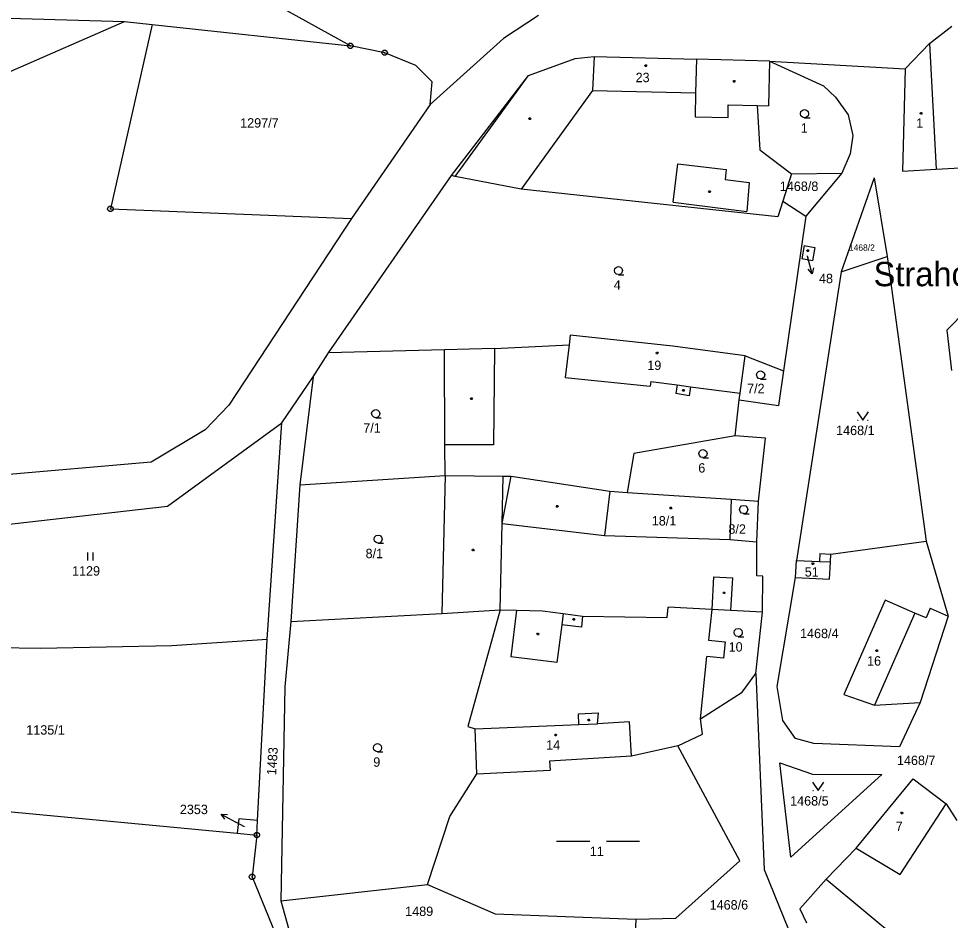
# Model space of a CAD drawing. Extents: x -852001 to -848657, y -1054973 to -1052182.
# Drawn here: x -850781 to -850612.8, y -1053593.3 to -1053430.4 of the extents above; entities that cross this region are included whole.
import ezdxf

# ---------------------------------------------------------------- set-up
doc = ezdxf.new("R2010")
doc.units = 0
for name, color, linetype in [('KN_HRANICE', 7, 'Continuous'), ('KN_KULTURY', 7, 'Continuous'), ('KN_MEZNIKY', 7, 'Continuous'), ('KN_PARCELY', 7, 'Continuous'), ('KN_SLUCKY', 7, 'Continuous'), ('KN_STAVEBNI', 7, 'Continuous')]:
    doc.layers.add(name, color=color, linetype=linetype)

# ---------------------------------------------------------------- blocks, each defined once
blk = doc.blocks.new('304')
blk.add_lwpolyline([(0, 0), (-0.38, 0.1), (-0.65, 0.37), (-0.75, 0.74), (-0.65, 1.11), (-0.38, 1.38), (-0.01, 1.48), (0.36, 1.38), (0.63, 1.11), (0.73, 0.73), (0.63, 0.35), (0.36, 0.08), (-0.02, -0.02), (0.98, -0.02)])
blk = doc.blocks.new('306')
for p, q in [((-0.5, 1.5), (-0.5, 0)), ((0.5, 0), (0.5, 1.5))]:
    blk.add_line(p, q)
blk = doc.blocks.new('314')
for p, q in [((-0.95, 0), (-0.85, 0)), ((0.85, 0), (0.95, 0))]:
    blk.add_line(p, q)
blk.add_lwpolyline([(-1, 1.5), (0, 0), (1, 1.5)])
blk = doc.blocks.new('803')
for p, q in [((-7.5, 0), (-1.5, 0)), ((1.5, 0), (7.5, 0))]:
    blk.add_line(p, q)
blk = doc.blocks.new('10292')
blk.add_line((0, 3), (0, 0))
blk.add_lwpolyline([(-0.5, 2), (0, 3), (0.5, 2)])
blk = doc.blocks.new('402')
blk.add_lwpolyline([(0.09, 0.15), (0.18, 0), (0.09, -0.15), (-0.09, -0.15), (-0.18, 0), (-0.09, 0.15), (0.09, 0.15)])
blk = doc.blocks.new('105')
blk.add_line((-0.12, 0), (0.12, 0))
blk.add_lwpolyline([(0.15, 0.48), (0.4, 0.3), (0.5, 0.01), (0.4, -0.28), (0.15, -0.46), (-0.16, -0.46), (-0.41, -0.28), (-0.51, 0.01), (-0.41, 0.3), (-0.16, 0.48), (0.15, 0.48)])

msp = doc.modelspace()

# ---------------------------------------------------------------- linework, layer by layer
at = {"layer": 'KN_HRANICE'}
for p, q in [((-850800.29, -1053429.81), (-850761.82, -1053430.94)), ((-850721.08, -1053435.35), (-850732.58, -1053428.94)), ((-850687.09, -1053429.83), (-850693.44, -1053434)), ((-850782.51, -1053439.96), (-850761.82, -1053430.94)), ((-850756.84, -1053431.48), (-850764.38, -1053464.76)), ((-850761.82, -1053430.94), (-850756.84, -1053431.48)), ((-850756.84, -1053431.48), (-850721.08, -1053435.35)), ((-850616.53, -1053434.88), (-850612.5, -1053431.79)), ((-850693.44, -1053434), (-850706.66, -1053445.91)), ((-850620.91, -1053439.48), (-850616.53, -1053434.88)), ((-850714.88, -1053436.58), (-850721.08, -1053435.35)), ((-850709.27, -1053438.86), (-850714.88, -1053436.58)), ((-850688.95, -1053440.66), (-850680.52, -1053437.6)), ((-850680.52, -1053437.6), (-850677.05, -1053437.23)), ((-850677.05, -1053437.23), (-850658.62, -1053437.73)), ((-850645.45, -1053438.08), (-850658.62, -1053437.73)), ((-850645.45, -1053438.08), (-850645.62, -1053446.16)), ((-850645.45, -1053438.08), (-850620.91, -1053439.48)), ((-850645.45, -1053438.08), (-850635.69, -1053442.58)), ((-850706.34, -1053441.84), (-850709.27, -1053438.86)), ((-850620.91, -1053439.48), (-850621.44, -1053457.94)), ((-850702.85, -1053458.77), (-850688.95, -1053440.66)), ((-850706.66, -1053445.91), (-850706.34, -1053441.84)), ((-850635.69, -1053442.58), (-850633.51, -1053444.61)), ((-850633.51, -1053444.61), (-850631.24, -1053447.76)), ((-850706.66, -1053445.91), (-850720.89, -1053466.48)), ((-850647.67, -1053446.12), (-850645.62, -1053446.16)), ((-850647.67, -1053446.12), (-850647.18, -1053454.08)), ((-850631.24, -1053447.76), (-850630.36, -1053451.52)), ((-850630.36, -1053451.52), (-850630.87, -1053454.82)), ((-850647.18, -1053454.08), (-850641.47, -1053458.44)), ((-850630.87, -1053454.82), (-850632.36, -1053458.32)), ((-850641.47, -1053458.44), (-850643.01, -1053463.36)), ((-850641.47, -1053458.44), (-850632.36, -1053458.32)), ((-850632.36, -1053458.32), (-850638.85, -1053466.06)), ((-850621.44, -1053457.94), (-850615.31, -1053457.61)), ((-850615.31, -1053457.61), (-850610.99, -1053457.38)), ((-850725.03, -1053490.78), (-850702.85, -1053458.77)), ((-850702.16, -1053458.9), (-850702.85, -1053458.77)), ((-850690.27, -1053461.21), (-850702.16, -1053458.9)), ((-850626.55, -1053459.18), (-850632.5, -1053476.14)), ((-850626.55, -1053459.18), (-850624.21, -1053473.39)), ((-850643.91, -1053466.23), (-850690.27, -1053461.21)), ((-850643.01, -1053463.36), (-850643.91, -1053466.23)), ((-850643.01, -1053463.36), (-850638.85, -1053466.06)), ((-850764.38, -1053464.76), (-850720.89, -1053466.48)), ((-850720.89, -1053466.48), (-850743, -1053500.2)), ((-850638.85, -1053466.06), (-850642.9, -1053493.99)), ((-850639.16, -1053471.38), (-850639.58, -1053473.8)), ((-850639.16, -1053471.38), (-850637.24, -1053471.72)), ((-850637.24, -1053471.72), (-850637.66, -1053474.13)), ((-850632.5, -1053476.14), (-850624.21, -1053473.39)), ((-850624.21, -1053473.39), (-850617.15, -1053524.78)), ((-850637.66, -1053474.13), (-850639.58, -1053473.8)), ((-850632.5, -1053476.14), (-850640.52, -1053528.25)), ((-850609.81, -1053482.98), (-850613.39, -1053486.7)), ((-850613.39, -1053486.7), (-850612.58, -1053493.95)), ((-850681.39, -1053487.58), (-850681.6, -1053489.34)), ((-850662.9, -1053489.55), (-850681.39, -1053487.58)), ((-850704.11, -1053490.22), (-850725.03, -1053490.78)), ((-850695.07, -1053489.98), (-850704.11, -1053490.22)), ((-850704, -1053507.36), (-850704.11, -1053490.22)), ((-850695.07, -1053489.98), (-850681.6, -1053489.34)), ((-850649.81, -1053491.29), (-850662.9, -1053489.55)), ((-850727.77, -1053495.08), (-850725.03, -1053490.78)), ((-850650.72, -1053498.08), (-850649.81, -1053491.29)), ((-850649.81, -1053491.29), (-850642.9, -1053493.99)), ((-850733.45, -1053503.39), (-850727.77, -1053495.08)), ((-850727.77, -1053495.08), (-850730.2, -1053514.63)), ((-850642.9, -1053493.99), (-850643.82, -1053500.3)), ((-850650.88, -1053499.27), (-850650.72, -1053498.08)), ((-850743, -1053500.2), (-850747.27, -1053504.66)), ((-850651.6, -1053505.78), (-850650.88, -1053499.27)), ((-850650.88, -1053499.27), (-850643.82, -1053500.3)), ((-850754.1, -1053518.43), (-850733.45, -1053503.39)), ((-850736.12, -1053542.56), (-850733.45, -1053503.39)), ((-850747.27, -1053504.66), (-850757.05, -1053510.53)), ((-850651.6, -1053505.78), (-850669.93, -1053508.92)), ((-850646.16, -1053506.15), (-850651.6, -1053505.78)), ((-850647.39, -1053517.55), (-850646.16, -1053506.15)), ((-850703.97, -1053512.92), (-850704, -1053507.36)), ((-850669.93, -1053508.92), (-850671.13, -1053515.98)), ((-850757.05, -1053510.53), (-850788.26, -1053513.24)), ((-850730.2, -1053514.63), (-850703.97, -1053512.92)), ((-850703.97, -1053512.92), (-850704.59, -1053537.84)), ((-850703.97, -1053512.92), (-850693.51, -1053513.03)), ((-850693.51, -1053513.03), (-850692.06, -1053513.04)), ((-850692.06, -1053513.04), (-850674.27, -1053515.78)), ((-850730.2, -1053514.63), (-850731.83, -1053539.3)), ((-850674.27, -1053515.78), (-850671.13, -1053515.98)), ((-850671.13, -1053515.98), (-850652.32, -1053517.19)), ((-850652.32, -1053517.19), (-850652.6, -1053524.47)), ((-850652.32, -1053517.19), (-850647.39, -1053517.55)), ((-850787.65, -1053522.28), (-850754.1, -1053518.43)), ((-850647.68, -1053524.87), (-850647.39, -1053517.55)), ((-850652.6, -1053524.47), (-850647.68, -1053524.87)), ((-850647.72, -1053531.05), (-850647.68, -1053524.87)), ((-850634.37, -1053527.13), (-850617.15, -1053524.78)), ((-850617.15, -1053524.78), (-850613.2, -1053538.34)), ((-850636.31, -1053527.03), (-850636.37, -1053528.43)), ((-850636.31, -1053527.03), (-850634.37, -1053527.13)), ((-850634.44, -1053528.52), (-850634.37, -1053527.13)), ((-850640.72, -1053531.35), (-850640.52, -1053528.25)), ((-850640.52, -1053528.25), (-850636.37, -1053528.43)), ((-850634.59, -1053531.62), (-850634.44, -1053528.52)), ((-850646.65, -1053531.12), (-850647.72, -1053531.05)), ((-850646.66, -1053537.61), (-850646.65, -1053531.12)), ((-850644.03, -1053551.05), (-850640.72, -1053531.35)), ((-850640.72, -1053531.35), (-850634.59, -1053531.62)), ((-850624.54, -1053535.45), (-850631.98, -1053552.46)), ((-850619.2, -1053537.77), (-850624.54, -1053535.45)), ((-850704.59, -1053537.84), (-850694.04, -1053537.19)), ((-850694.04, -1053537.19), (-850699.87, -1053558.24)), ((-850694.04, -1053537.19), (-850691.08, -1053537.27)), ((-850691.08, -1053537.27), (-850686.4, -1053537.34)), ((-850686.4, -1053537.34), (-850682.66, -1053537.85)), ((-850663.91, -1053538.55), (-850663.74, -1053536.68)), ((-850655.85, -1053537.11), (-850663.74, -1053536.68)), ((-850655.85, -1053537.11), (-850656.41, -1053542.64)), ((-850652.38, -1053537.3), (-850655.85, -1053537.11)), ((-850646.66, -1053537.61), (-850652.38, -1053537.3)), ((-850616.4, -1053536.9), (-850617.16, -1053538.65)), ((-850616.4, -1053536.9), (-850613.2, -1053538.34)), ((-850731.83, -1053539.3), (-850704.59, -1053537.84)), ((-850682.66, -1053537.85), (-850679.16, -1053538.32)), ((-850679.16, -1053538.32), (-850663.91, -1053538.55)), ((-850647.89, -1053548.68), (-850646.66, -1053537.61)), ((-850617.16, -1053538.65), (-850619.2, -1053537.77)), ((-850613.2, -1053538.34), (-850618.2, -1053553.93)), ((-850731.83, -1053539.3), (-850732.9, -1053551.1)), ((-850736.12, -1053542.56), (-850753.31, -1053543.66)), ((-850737.82, -1053575.23), (-850736.12, -1053542.56)), ((-850776.98, -1053544.19), (-850811.29, -1053543.49)), ((-850753.31, -1053543.66), (-850776.98, -1053544.19)), ((-850656.41, -1053542.64), (-850653.42, -1053542.95)), ((-850653.42, -1053542.95), (-850653.72, -1053545.93)), ((-850657.85, -1053556.86), (-850656.71, -1053545.63)), ((-850653.72, -1053545.93), (-850656.71, -1053545.63)), ((-850650.36, -1053552.02), (-850647.89, -1053548.68)), ((-850647.89, -1053548.68), (-850646.41, -1053584.08)), ((-850732.9, -1053551.1), (-850733.6, -1053589.76)), ((-850657.85, -1053556.86), (-850650.36, -1053552.02)), ((-850643.02, -1053557.16), (-850644.03, -1053551.05)), ((-850631.98, -1053552.46), (-850626.47, -1053554.4)), ((-850626.47, -1053554.4), (-850618.2, -1053553.93)), ((-850618.2, -1053553.93), (-850621.95, -1053561.95)), ((-850657.53, -1053559.65), (-850657.85, -1053556.86)), ((-850640.75, -1053560.43), (-850643.02, -1053557.16)), ((-850699.87, -1053558.24), (-850698.57, -1053558.66)), ((-850698.25, -1053566.82), (-850698.57, -1053558.66)), ((-850661.96, -1053561.72), (-850657.53, -1053559.65)), ((-850637.41, -1053561.33), (-850640.75, -1053560.43)), ((-850661.96, -1053561.72), (-850670.36, -1053563.6)), ((-850650.8, -1053582.53), (-850661.96, -1053561.72)), ((-850621.95, -1053561.95), (-850637.41, -1053561.33)), ((-850670.36, -1053563.6), (-850685.16, -1053564.49)), ((-850685.16, -1053564.49), (-850684.99, -1053566.13)), ((-850698.25, -1053566.82), (-850684.99, -1053566.13)), ((-850643.55, -1053564.8), (-850637.64, -1053566.88)), ((-850641.59, -1053581.86), (-850643.55, -1053564.8)), ((-850703.1, -1053574.48), (-850698.25, -1053566.82)), ((-850625.16, -1053566.93), (-850641.59, -1053581.86)), ((-850637.64, -1053566.88), (-850625.16, -1053566.93)), ((-850629.75, -1053580.2), (-850619.47, -1053567.69)), ((-850619.47, -1053567.69), (-850613.54, -1053572.2)), ((-850819.36, -1053570.11), (-850741.49, -1053577.51)), ((-850613.54, -1053572.2), (-850611.6, -1053575.23)), ((-850707.14, -1053586.78), (-850703.1, -1053574.48)), ((-850741.22, -1053574.92), (-850741.49, -1053577.51)), ((-850737.82, -1053575.23), (-850741.22, -1053574.92)), ((-850737.96, -1053577.85), (-850737.82, -1053575.23)), ((-850741.49, -1053577.51), (-850737.96, -1053577.85)), ((-850737.96, -1053577.85), (-850738.81, -1053585.42)), ((-850635.17, -1053585.8), (-850629.75, -1053580.2)), ((-850662.32, -1053592.86), (-850650.8, -1053582.53)), ((-850646.41, -1053584.08), (-850639.44, -1053601.2)), ((-850738.81, -1053585.42), (-850734.66, -1053595.56)), ((-850639.95, -1053591.18), (-850635.17, -1053585.8)), ((-850635.17, -1053585.8), (-850612.97, -1053604.25)), ((-850733.6, -1053589.76), (-850707.14, -1053586.78)), ((-850707.14, -1053586.78), (-850694.94, -1053592.06)), ((-850733.6, -1053589.76), (-850732.16, -1053594.91)), ((-850639.95, -1053591.18), (-850638.77, -1053593.71)), ((-850694.94, -1053592.06), (-850669.55, -1053593.05)), ((-850669.55, -1053593.05), (-850669.76, -1053598.34)), ((-850669.55, -1053593.05), (-850662.32, -1053592.86))]:
    msp.add_line(p, q, dxfattribs=at)
at = {"layer": 'KN_PARCELY'}
for p, q in [((-850638.6, -1053473.28), (-850638.51, -1053473.6)), ((-850740.16, -1053576.38), (-850741.76, -1053575.51))]:
    msp.add_line(p, q, dxfattribs=at)
at = {"layer": 'KN_SLUCKY'}
for p, q in [((-850616.53, -1053434.88), (-850615.31, -1053457.61)), ((-850677.05, -1053437.23), (-850677.39, -1053443.4)), ((-850658.62, -1053437.73), (-850658.75, -1053443.79)), ((-850702.16, -1053458.9), (-850688.95, -1053440.66)), ((-850677.39, -1053443.4), (-850690.27, -1053461.21)), ((-850677.39, -1053443.4), (-850658.75, -1053443.79)), ((-850658.75, -1053443.79), (-850658.84, -1053448.14)), ((-850652.91, -1053448.26), (-850652.86, -1053446.01)), ((-850652.86, -1053446.01), (-850647.67, -1053446.12)), ((-850658.84, -1053448.14), (-850652.91, -1053448.26)), ((-850662.83, -1053463.54), (-850661.97, -1053456.66)), ((-850661.97, -1053456.66), (-850653.22, -1053457.69)), ((-850653.22, -1053457.69), (-850653.42, -1053459.46)), ((-850653.42, -1053459.46), (-850649.08, -1053460.02)), ((-850649.08, -1053460.02), (-850649.51, -1053465.22)), ((-850662.83, -1053463.54), (-850649.51, -1053465.22)), ((-850695.07, -1053489.98), (-850695.27, -1053507.36)), ((-850681.6, -1053489.34), (-850682.31, -1053495.23)), ((-850682.31, -1053495.23), (-850666.96, -1053496.77)), ((-850666.87, -1053495.92), (-850666.96, -1053496.77)), ((-850666.87, -1053495.92), (-850662.07, -1053496.56)), ((-850662.07, -1053496.56), (-850662.33, -1053498.14)), ((-850662.07, -1053496.56), (-850659.66, -1053496.88)), ((-850659.66, -1053496.88), (-850659.93, -1053498.53)), ((-850659.66, -1053496.88), (-850650.72, -1053498.08)), ((-850659.93, -1053498.53), (-850662.33, -1053498.14)), ((-850695.27, -1053507.36), (-850704, -1053507.36)), ((-850693.65, -1053521.56), (-850693.51, -1053513.03)), ((-850693.65, -1053521.56), (-850692.06, -1053513.04)), ((-850674.27, -1053515.78), (-850675.21, -1053523.73)), ((-850694.04, -1053537.19), (-850693.65, -1053521.56)), ((-850693.65, -1053521.56), (-850675.21, -1053523.73)), ((-850675.21, -1053523.73), (-850652.6, -1053524.47)), ((-850636.37, -1053528.43), (-850634.44, -1053528.52)), ((-850655.53, -1053531.23), (-850655.85, -1053537.11)), ((-850655.53, -1053531.23), (-850652.07, -1053531.41)), ((-850652.38, -1053537.3), (-850652.07, -1053531.41)), ((-850691.08, -1053537.27), (-850692.14, -1053545.65)), ((-850682.66, -1053537.85), (-850682.92, -1053539.86)), ((-850679.16, -1053538.32), (-850679.35, -1053540.32)), ((-850619.2, -1053537.77), (-850626.47, -1053554.4)), ((-850682.92, -1053539.86), (-850683.79, -1053546.71)), ((-850679.35, -1053540.32), (-850682.92, -1053539.86)), ((-850683.79, -1053546.71), (-850692.14, -1053545.65)), ((-850679.9, -1053555.97), (-850676.31, -1053555.78)), ((-850679.82, -1053557.89), (-850679.9, -1053555.97)), ((-850676.44, -1053557.75), (-850676.31, -1053555.78)), ((-850679.82, -1053557.89), (-850676.44, -1053557.75)), ((-850670.7, -1053557.4), (-850676.44, -1053557.75)), ((-850670.36, -1053563.6), (-850670.7, -1053557.4)), ((-850698.57, -1053558.66), (-850679.82, -1053557.89)), ((-850621.84, -1053585), (-850613.54, -1053572.2)), ((-850629.75, -1053580.2), (-850621.84, -1053585))]:
    msp.add_line(p, q, dxfattribs=at)
at = {"layer": 'KN_STAVEBNI'}
for p, q in [((-850620.91, -1053439.48), (-850616.53, -1053434.88)), ((-850616.53, -1053434.88), (-850615.31, -1053457.61)), ((-850677.05, -1053437.23), (-850677.39, -1053443.4)), ((-850677.05, -1053437.23), (-850658.62, -1053437.73)), ((-850658.62, -1053437.73), (-850658.75, -1053443.79)), ((-850620.91, -1053439.48), (-850621.44, -1053457.94)), ((-850677.39, -1053443.4), (-850658.75, -1053443.79)), ((-850621.44, -1053457.94), (-850615.31, -1053457.61)), ((-850639.16, -1053471.38), (-850639.58, -1053473.8)), ((-850639.16, -1053471.38), (-850637.24, -1053471.72)), ((-850637.24, -1053471.72), (-850637.66, -1053474.13)), ((-850637.66, -1053474.13), (-850639.58, -1053473.8)), ((-850681.39, -1053487.58), (-850681.6, -1053489.34)), ((-850662.9, -1053489.55), (-850681.39, -1053487.58)), ((-850681.6, -1053489.34), (-850682.31, -1053495.23)), ((-850649.81, -1053491.29), (-850662.9, -1053489.55)), ((-850650.72, -1053498.08), (-850649.81, -1053491.29)), ((-850682.31, -1053495.23), (-850666.96, -1053496.77)), ((-850666.87, -1053495.92), (-850666.96, -1053496.77)), ((-850666.87, -1053495.92), (-850662.07, -1053496.56)), ((-850662.07, -1053496.56), (-850659.66, -1053496.88)), ((-850659.66, -1053496.88), (-850650.72, -1053498.08)), ((-850674.27, -1053515.78), (-850675.21, -1053523.73)), ((-850674.27, -1053515.78), (-850671.13, -1053515.98)), ((-850671.13, -1053515.98), (-850652.32, -1053517.19)), ((-850652.32, -1053517.19), (-850652.6, -1053524.47)), ((-850675.21, -1053523.73), (-850652.6, -1053524.47)), ((-850640.72, -1053531.35), (-850640.52, -1053528.25)), ((-850640.52, -1053528.25), (-850636.37, -1053528.43)), ((-850636.37, -1053528.43), (-850634.44, -1053528.52)), ((-850634.59, -1053531.62), (-850634.44, -1053528.52)), ((-850640.72, -1053531.35), (-850634.59, -1053531.62)), ((-850624.54, -1053535.45), (-850631.98, -1053552.46)), ((-850619.2, -1053537.77), (-850624.54, -1053535.45)), ((-850619.2, -1053537.77), (-850626.47, -1053554.4)), ((-850631.98, -1053552.46), (-850626.47, -1053554.4)), ((-850679.82, -1053557.89), (-850676.44, -1053557.75)), ((-850670.7, -1053557.4), (-850676.44, -1053557.75)), ((-850670.36, -1053563.6), (-850670.7, -1053557.4)), ((-850698.57, -1053558.66), (-850679.82, -1053557.89)), ((-850698.25, -1053566.82), (-850698.57, -1053558.66)), ((-850670.36, -1053563.6), (-850685.16, -1053564.49)), ((-850685.16, -1053564.49), (-850684.99, -1053566.13)), ((-850698.25, -1053566.82), (-850684.99, -1053566.13)), ((-850629.75, -1053580.2), (-850619.47, -1053567.69)), ((-850619.47, -1053567.69), (-850613.54, -1053572.2)), ((-850621.84, -1053585), (-850613.54, -1053572.2)), ((-850629.75, -1053580.2), (-850621.84, -1053585))]:
    msp.add_line(p, q, dxfattribs=at)

# ---------------------------------------------------------------- block references
at = {"layer": 'KN_KULTURY'}
for name, p in [('402', (-850667.76, -1053438.91)), ('402', (-850651.8, -1053441.74)), ('402', (-850688.69, -1053448.47)), ('304', (-850639.09, -1053448.32)), ('402', (-850618.07, -1053447.5)), ('402', (-850656.24, -1053461.68)), ('402', (-850638.51, -1053472.33)), ('304', (-850672.68, -1053476.65)), ('402', (-850665.71, -1053490.82)), ('304', (-850647.02, -1053495.49)), ('402', (-850660.97, -1053497.53)), ('402', (-850699.23, -1053499.06)), ('304', (-850716.49, -1053502.48)), ('314', (-850628.58, -1053502.92)), ('304', (-850657.43, -1053509.7)), ('402', (-850683.74, -1053518.46)), ('402', (-850663.26, -1053518.77)), ('304', (-850650.08, -1053519.8)), ('304', (-850716.06, -1053525.15)), ('306', (-850768, -1053528.3)), ('402', (-850698.92, -1053526.37)), ('402', (-850637.59, -1053528.85)), ('402', (-850653.63, -1053534.11)), ('402', (-850680.76, -1053538.87)), ('304', (-850651.06, -1053542.02)), ('402', (-850687.21, -1053541.57)), ('402', (-850626.07, -1053544.55)), ('402', (-850678.05, -1053557.06)), ('402', (-850684.02, -1053559.79)), ('304', (-850716.17, -1053562.82)), ('314', (-850636.64, -1053569.83)), ('402', (-850621.52, -1053573.87)), ('803', (-850676.36, -1053578.94))]:
    msp.add_blockref(name, p, dxfattribs=at)
at = {"layer": 'KN_MEZNIKY'}
for p in [(-850721.08, -1053435.35), (-850714.88, -1053436.58), (-850764.38, -1053464.76), (-850737.96, -1053577.85), (-850738.81, -1053585.42)]:
    msp.add_blockref('105', p, dxfattribs=at)
at = {"layer": 'KN_PARCELY'}
for p, rotation in [((-850638.51, -1053473.6), -164.90787100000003), ((-850741.76, -1053575.51), 61.36378000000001)]:
    msp.add_blockref('10292', p, dxfattribs=dict(at, rotation=rotation))

# ---------------------------------------------------------------- texts
for s, height, p in [('23', 1.7, (-850669.59, -1053441.89)), ('1297/7', 1.7, (-850740.97, -1053450.1)), ('1', 1.7, (-850618.94, -1053450.13)), ('1', 1.7, (-850639.78, -1053451.02)), ('1468/8', 1.7, (-850643.56, -1053461.54)), ('1468/2', 1.14, (-850631.08, -1053472.34)), ('48', 0.1, (-850638.7, -1053473.28)), ('Strahov', 4.4, (-850626.63, -1053478.74)), ('48', 1.7, (-850636.49, -1053478.2)), ('4', 1.7, (-850673.53, -1053479.35)), ('19', 1.7, (-850667.48, -1053493.87)), ('7/2', 1.7, (-850649.47, -1053498.06)), ('7/1', 1.7, (-850718.76, -1053505.18)), ('1468/1', 1.7, (-850633.4, -1053505.62)), ('6', 1.7, (-850658.28, -1053512.4)), ('18/1', 1.7, (-850666.67, -1053521.95)), ('8/2', 1.7, (-850652.84, -1053523.44)), ('8/1', 1.7, (-850718.33, -1053527.85)), ('1129', 1.7, (-850771.32, -1053531)), ('51', 1.7, (-850639.06, -1053531.18)), ('1468/4', 1.7, (-850639.91, -1053542.29)), ('10', 1.7, (-850652.8, -1053544.72)), ('16', 1.7, (-850627.81, -1053547.25)), ('1135/1', 1.7, (-850779.58, -1053559.72)), ('14', 1.7, (-850685.73, -1053562.43)), ('9', 1.7, (-850716.94, -1053565.52)), ('1468/7', 1.7, (-850622.42, -1053565.21)), ('1468/5', 1.7, (-850641.7, -1053572.53)), ('2353', 1.7, (-850751.86, -1053574.07)), ('7', 1.7, (-850622.64, -1053577.11)), ('2353', 0.1, (-850740.35, -1053576.38)), ('11', 1.7, (-850677.86, -1053581.64)), ('1468/6', 1.7, (-850656.23, -1053591.31)), ('1489', 1.7, (-850711.18, -1053592.47))]:
    msp.add_text(s, height=height, dxfattribs=at).set_placement(p)
msp.add_text('1483', height=1.7, rotation=86.116, dxfattribs=at).set_placement((-850734.49, -1053567.09))

doc.saveas('drawing.dxf')
